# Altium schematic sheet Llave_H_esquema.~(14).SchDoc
size A4
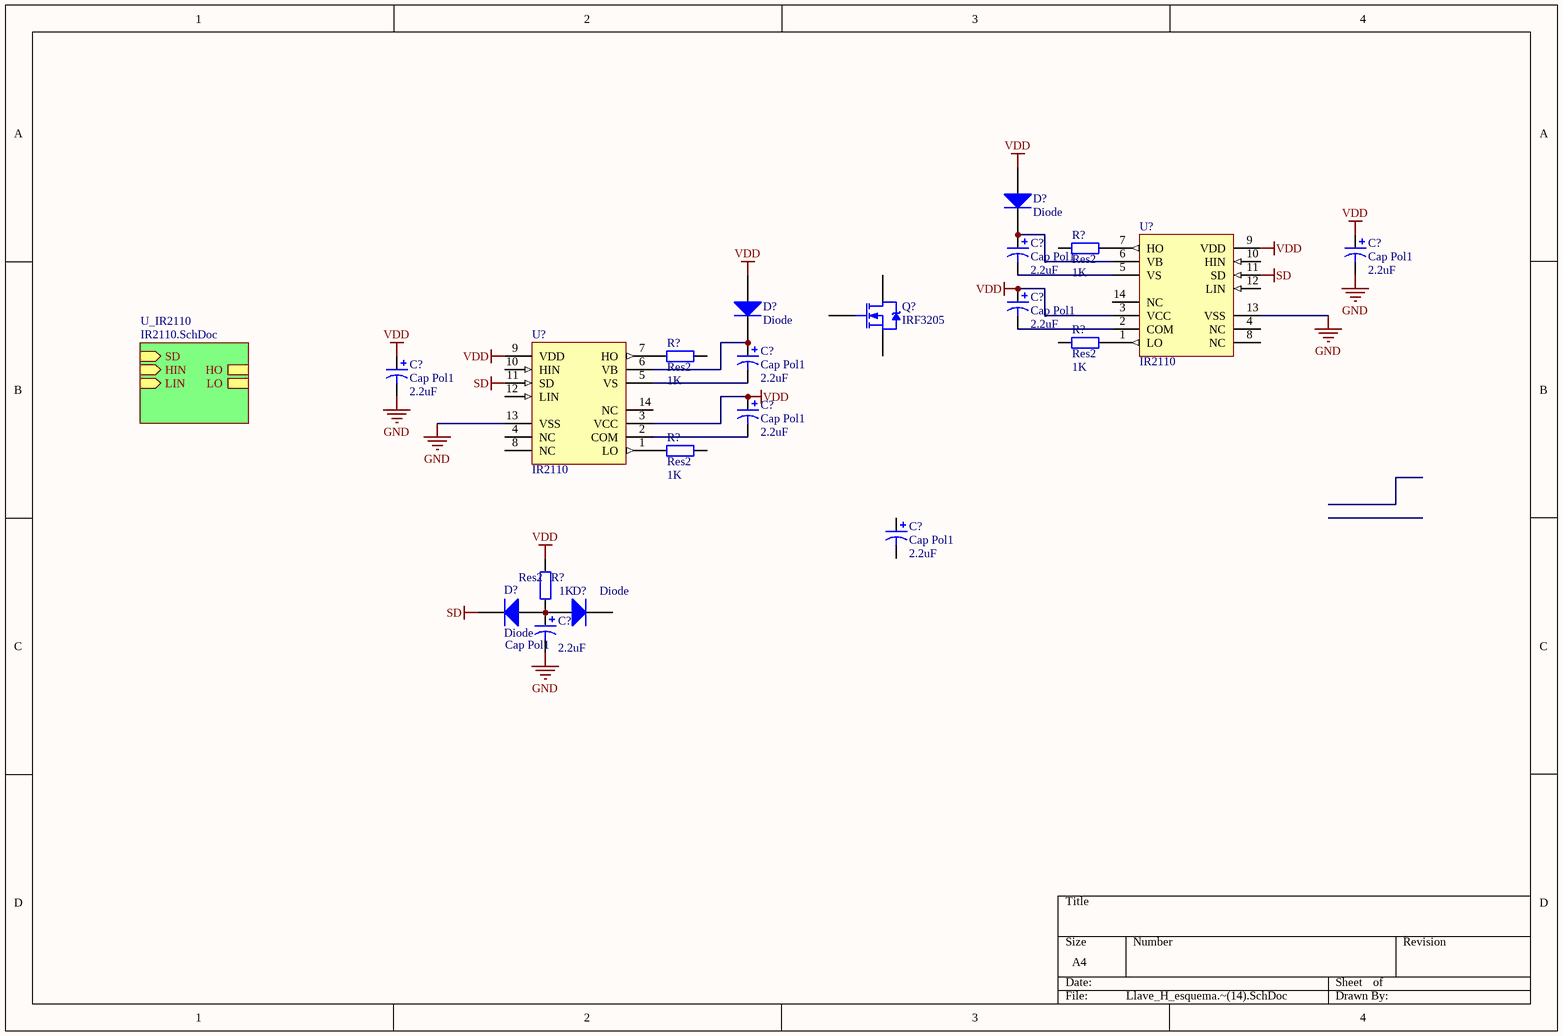
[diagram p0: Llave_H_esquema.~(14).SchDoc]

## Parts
(Parts that share a designator on the sheet are numbered #1, #2 ... from top to bottom, then left to right.)
C?#1  Cap Pol1  value 2.2uF  [RB7.6-15]
C?#2  Cap Pol1  value 2.2uF  [RB7.6-15]
C?#3  Cap Pol1  value 2.2uF  [RB7.6-15]
C?#4  Cap Pol1  value 2.2uF  [RB7.6-15]
C?#5  Cap Pol1  value 2.2uF  [RB7.6-15]
C?#6  Cap Pol1  value 2.2uF  [RB7.6-15]
C?#7  Cap Pol1  value 2.2uF  [RB7.6-15]
C?#8  Cap Pol1  value 2.2uF  [RB7.6-15]
D?#1  Diode  [SMC]
D?#2  Diode  [SMC]
D?#3  Diode  [SMC]
D?#4  Diode  [SMC]
Q?  IRF3205  [TO-220AB]
R?#1  Res2  value 1K  [AXIAL-0.4]
R?#2  Res2  value 1K  [AXIAL-0.4]
R?#3  Res2  value 1K  [AXIAL-0.4]
R?#4  Res2  value 1K  [AXIAL-0.4]
R?#5  Res2  value 1K  [AXIAL-0.4]
U?#1  IR2110  [PDIP14]
U?#2  IR2110  [PDIP14]

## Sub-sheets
U_IR2110 = IR2110.SchDoc: SD (in), HIN (in), LIN (in), HO, LO

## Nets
GND: C?#2.2 C?#5.2 C?#8.2 U?#1.13(VSS) U?#2.13(VSS)
SD: D?#4.2(K) U?#1.11(SD) U?#2.11(SD)
VDD: C?#2.1 C?#3.1 C?#5.1 C?#6.1 D?#1.1(A) D?#2.1(A) R?#5.2 U?#1.3(VCC) U?#1.9(VDD) U?#2.3(VCC) U?#2.9(VDD)
NetC?#1_1: C?#1.1 D?#1.2(K) U?#1.6(VB)
NetC?#1_2: C?#1.2 U?#1.5(VS)
NetC?#3_2: C?#3.2 U?#1.2(COM)
NetC?#4_1: C?#4.1 D?#2.2(K) U?#2.6(VB)
NetC?#4_2: C?#4.2 U?#2.5(VS)
NetC?#6_2: C?#6.2 U?#2.2(COM)
NetC?#8_1: C?#8.1 D?#3.1(A) D?#4.1(A) R?#5.1
NetR?#1_2: R?#1.2 U?#1.7(HO)
NetR?#2_2: R?#2.2 U?#1.1(LO)
NetR?#3_1: R?#3.1 U?#2.7(HO)
NetR?#4_1: R?#4.1 U?#2.1(LO)

Not connected (* = marked no-connect by the designer): C?#7 1 2; D?#3 2(K); Q? 1(G) 2(D) 3(S); R?#1 1; R?#2 1; R?#3 2; R?#4 2; U?#1 4(NC) 8(NC) 10(HIN) 12(LIN) 14(NC); U?#2 4(NC) 8(NC) 10(HIN) 12(LIN) 14(NC)

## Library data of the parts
C?#1-C?#8 = Cap Pol1: Polarized Capacitor (Radial)
D?#1-D?#4 = Diode: Default Diode
Q? = IRF3205: HEXFET Power MOSFET; Note: Pin 2 is electrically connected to pin 4.
R?#1-R?#5 = Res2: Resistor
U?#1 U?#2 = IR2110: High and Low Side Driver; Note: Pins 4, 8 and 14 are not connected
